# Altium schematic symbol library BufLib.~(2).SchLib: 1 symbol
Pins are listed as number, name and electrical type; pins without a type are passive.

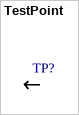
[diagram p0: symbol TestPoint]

## TestPoint
designator TP?  (value not drawn)
pins: 0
